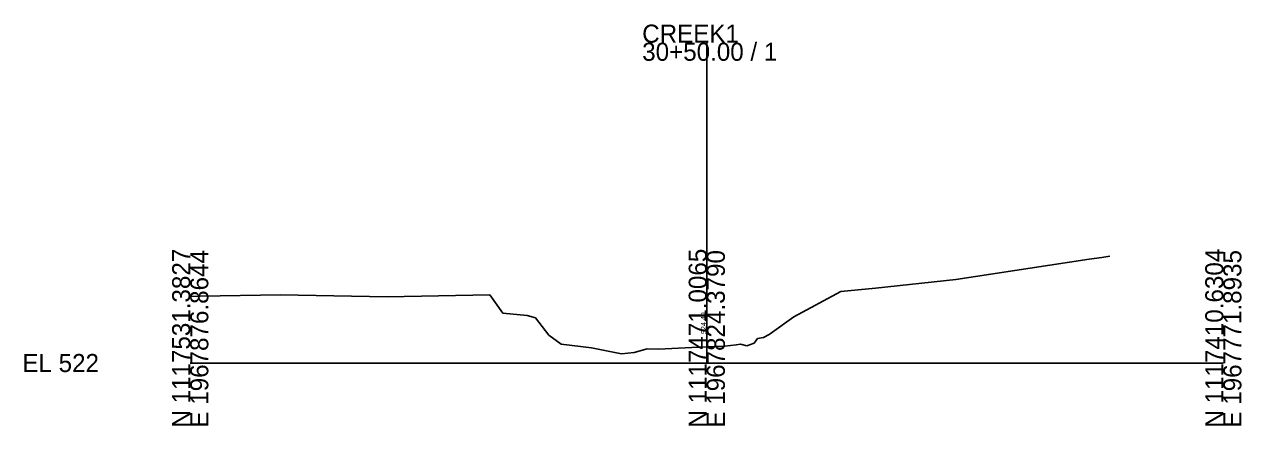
# Model space of a CAD drawing. Extents: x -26 to 163, y -10 to 10052.
# Drawn here: x -25.7 to 162.8, y 9990.3 to 10052.4 of the extents above; entities that cross this region are included whole.
import ezdxf

# ---------------------------------------------------------------- set-up
doc = ezdxf.new("R2010")
doc.units = 0
for name, color, linetype in [('RD_GPK_XS_Cell', 7, 'Continuous'), ('RD_XS_ExGround', 7, 'Continuous'), ('RD_XS_TX_Elev_EX', 7, 'Continuous')]:
    doc.layers.add(name, color=color, linetype=linetype)

msp = doc.modelspace()

# ---------------------------------------------------------------- linework, layer by layer
at = {"layer": 'RD_GPK_XS_Cell'}
for p, q in [((80, 10000), (80, 10049.58)), ((0, 10000), (80, 10000)), ((80, 10000), (160, 10000))]:
    msp.add_line(p, q, dxfattribs=at)
at = {"layer": 'RD_XS_ExGround'}
for p, q in [((118.59, 10012.94), (139.21, 10016.06)), ((139.21, 10016.06), (141.17, 10016.33)), ((141.17, 10016.33), (142.41, 10016.53)), ((93.5, 10007.14), (100.78, 10011.08)), ((100.78, 10011.08), (106.15, 10011.56)), ((106.15, 10011.56), (118.59, 10012.94)), ((0, 10010.31), (1.55, 10010.34)), ((1.55, 10010.34), (13.99, 10010.55)), ((13.99, 10010.55), (30.52, 10010.23)), ((30.52, 10010.23), (46.4, 10010.54)), ((46.4, 10010.54), (48.43, 10007.74)), ((48.43, 10007.74), (52.2, 10007.35)), ((52.2, 10007.35), (53.49, 10006.98)), ((53.49, 10006.98), (55.55, 10004.33)), ((89.65, 10004.4), (93.5, 10007.14)), ((55.55, 10004.33), (57.44, 10002.9)), ((87.36, 10003.08), (87.86, 10003.77)), ((87.86, 10003.77), (88.78, 10003.95)), ((88.78, 10003.95), (89.65, 10004.4)), ((57.44, 10002.9), (62.16, 10002.36)), ((62.16, 10002.36), (66.81, 10001.41)), ((68.75, 10001.61), (70.77, 10002.22)), ((70.77, 10002.22), (72.54, 10002.15)), ((72.54, 10002.15), (77.68, 10002.4)), ((77.68, 10002.4), (80, 10002.49)), ((80, 10002.49), (82.79, 10002.59)), ((82.79, 10002.59), (84.53, 10002.79)), ((84.53, 10002.79), (85.22, 10002.91)), ((85.22, 10002.91), (86.18, 10002.64)), ((86.18, 10002.64), (87.36, 10003.08)), ((66.81, 10001.41), (68.75, 10001.61))]:
    msp.add_line(p, q, dxfattribs=at)

# ---------------------------------------------------------------- texts
at = {"layer": 'RD_GPK_XS_Cell'}
for s, p in [('CREEK1', (70, 10049.58)), ('30+50.00 / 1', (70, 10046.78)), ('EL 522', (-26, 9998.6))]:
    msp.add_text(s, height=2.8, dxfattribs=at).set_placement(p)
for s, p in [('N 1117531.3827', (0, 9990)), ('E 1967876.8644', (2.8, 9990)), ('N 1117471.0065', (80, 9990)), ('E 1967824.3790', (82.8, 9990)), ('N 1117410.6304', (160, 9990)), ('E 1967771.8935', (162.8, 9990))]:
    msp.add_text(s, height=2.8, rotation=90, dxfattribs=at).set_placement(p)
at = {"layer": 'RD_XS_TX_Elev_EX'}
msp.add_text('524.49', height=0.8, rotation=90, dxfattribs=at).set_placement((79.9, 10004.49))

doc.saveas('drawing.dxf')
